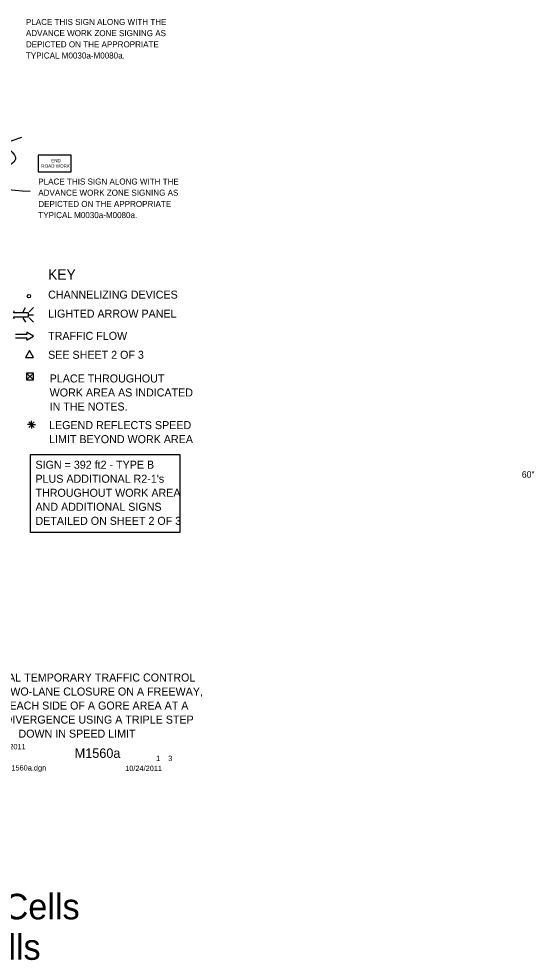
# Model space of a CAD drawing. Extents: x 16552 to 19508, y 5713 to 7079.
# Drawn here: x 17224 to 17823, y 5713 to 6807 of the extents above; entities that cross this region are included whole.
import ezdxf

# ---------------------------------------------------------------- set-up
doc = ezdxf.new("R2010")
doc.units = 0
for name, color, linetype in [('BORDER', 7, 'Continuous'), ('BORDER_SIGNAL_WO', 7, 'Continuous'), ('MT_SCRATCH_LEVEL_E', 7, 'Continuous'), ('PAVT_EDGE_EX', 7, 'Continuous'), ('TRAFFIC_SIGNS_PR', 7, 'Continuous'), ('TYPICAL_TEXT_DIMEN_EX', 7, 'Continuous'), ('TYPICAL_TEXT_DIMEN_PR', 7, 'Continuous')]:
    doc.layers.add(name, color=color, linetype=linetype)

msp = doc.modelspace()

# ---------------------------------------------------------------- linework, layer by layer
at = {"layer": 'MT_SCRATCH_LEVEL_E'}
for p, q in [((17233.4, 6441.9), (17233.7, 6440.1)), ((17241.3, 6438.3), (17234.1, 6442.4)), ((17233.7, 6440.1), (17220.5, 6440.1)), ((17220.5, 6436.4), (17233.7, 6436.4)), ((17233.7, 6436.4), (17233.4, 6434.6)), ((17234.1, 6434.1), (17241.3, 6438.3))]:
    msp.add_line(p, q, dxfattribs=at)
for centre, start, end in [((17233.9, 6442), 60.4248, 189.9638), ((17233.9, 6434.5), 170.0362, 299.7731)]:
    msp.add_arc(centre, 0.463, start, end, dxfattribs=at)
at = {"layer": 'PAVT_EDGE_EX'}
msp.add_arc((17319.9, 6383.8), 300, 107.923, 180, dxfattribs=at)
at = {"layer": 'TRAFFIC_SIGNS_PR'}
for p, q in [((17229.5, 6466.7), (17232.3, 6471.6)), ((17236.4, 6466.7), (17241.3, 6471.6)), ((17236.4, 6463.2), (17241.3, 6463.2)), ((17232.4, 6454.7), (17229.5, 6459.6)), ((17236.4, 6459.6), (17241.3, 6454.7))]:
    msp.add_line(p, q, dxfattribs=at)
msp.add_lwpolyline([(17246.9, 6629.2), (17285.3, 6629.2), (17285.3, 6648.4), (17246.9, 6648.4)], close=True, dxfattribs=at)
msp.add_lwpolyline([(17219.1, 6458.5), (17218.7, 6460.7), (17235.7, 6460.7), (17235.7, 6465.5), (17218.7, 6465.5), (17219.1, 6467.8)], dxfattribs=at)
msp.add_circle((17236.1, 6484.8), 2, dxfattribs=at)
at = {"layer": 'TYPICAL_TEXT_DIMEN_EX'}
msp.add_lwpolyline([(17237.9, 6300.7), (17411.6, 6300.7), (17411.6, 6210.4), (17237.9, 6210.4)], close=True, dxfattribs=at)
at = {"layer": 'TYPICAL_TEXT_DIMEN_PR'}
for p, q in [((17233.4, 6395.4), (17241.4, 6387.4)), ((17233.4, 6387.4), (17241.4, 6395.4)), ((17239.1, 6335.5), (17234.6, 6335.5)), ((17236, 6338.7), (17242.3, 6332.3)), ((17242.3, 6338.7), (17236, 6332.3)), ((17239.1, 6335.5), (17239.1, 6340)), ((17239.1, 6335.5), (17242.3, 6335.5)), ((17239.1, 6335.5), (17243.6, 6335.5)), ((17239.1, 6335.5), (17239.1, 6331))]:
    msp.add_line(p, q, dxfattribs=at)
for points in [[(17236.8, 6421.5), (17232.3, 6413.6), (17241.4, 6413.6)], [(17233.4, 6395.4), (17233.4, 6387.4), (17241.4, 6387.4), (17241.4, 6395.4)]]:
    msp.add_lwpolyline(points, close=True, dxfattribs=at)
msp.add_open_spline([(17211.5, 6657), (17216.4, 6652.5), (17226.4, 6643.1), (17205.5, 6632.6), (17175.7, 6610.9), (17212.4, 6608.3), (17237.4, 6606.6)], degree=3, dxfattribs=at)

# ---------------------------------------------------------------- texts
at = {"layer": 'BORDER'}
for s, p in [('TYPICAL TEMPORARY TRAFFIC CONTROL', (17175.2, 6037.1)), ('FOR A TWO-LANE CLOSURE ON A FREEWAY,', (17165.4, 6020.8)), ('ONE ON EACH SIDE OF A GORE AREA AT A ', (17160.9, 6004.5)), ('MAJOR DIVERGENCE USING A TRIPLE STEP ', (17160.9, 5988.2)), ('DOWN IN SPEED LIMIT', (17223.9, 5971.9))]:
    msp.add_text(s, height=9.3, dxfattribs=at).set_placement(p)
at = {"layer": 'BORDER_SIGNAL_WO'}
for s, height, p in [('    OCTOBER 2011    ', 6.2, (17159.1, 5958.3)), ('    M1560a   ', 11, (17272.9, 5948.4)), (' 1    3 ', 6.2, (17381.4, 5944.7)), ('PW RD/TS/Typicals/Signs/MT FWY/M1560a.dgn      ', 6.2, (17070.6, 5933.7)), ('10/24/2011    ', 6.2, (17347.9, 5933.1)), ('AS = 0.8 for Sign Cells', 29.727, (16894, 5760.8)), ('     1.0 for Text Cells', 29.727, (16894, 5713.8))]:
    msp.add_text(s, height=height, dxfattribs=at).set_placement(p)
at = {"layer": 'TRAFFIC_SIGNS_PR'}
for s, height, p in [('PLACE THIS SIGN ALONG WITH THE', 7, (17232.6, 6799.8)), ('ADVANCE WORK ZONE SIGNING AS', 7, (17232.6, 6786.8)), ('DEPICTED ON THE APPROPRIATE', 7, (17232.6, 6773.8)), ('TYPICAL M0030a-M0080a.', 7, (17232.6, 6760.8)), ('ROAD WORK', 3.83, (17250.5, 6634)), ('END', 3.83, (17261.9, 6640.3)), ('PLACE THIS SIGN ALONG WITH THE', 7, (17247, 6614.4)), ('ADVANCE WORK ZONE SIGNING AS', 7, (17247, 6601.4)), ('DEPICTED ON THE APPROPRIATE', 7, (17247, 6588.4)), ('TYPICAL M0030a-M0080a.', 7, (17247, 6575.4))]:
    msp.add_text(s, height=height, dxfattribs=at).set_placement(p)
at = {"layer": 'TYPICAL_TEXT_DIMEN_EX'}
for s, height, p in [('KEY', 12, (17258.4, 6503.9)), ('CHANNELIZING DEVICES', 9.3, (17258.4, 6481.9)), ('LIGHTED ARROW PANEL', 9.3, (17258.4, 6459.8)), ('TRAFFIC FLOW', 9.3, (17258.4, 6434)), ('SEE SHEET 2 OF 3', 9.3, (17258.4, 6412)), ('PLACE THROUGHOUT', 9.3, (17260.2, 6384.5)), ('WORK AREA AS INDICATED', 9.3, (17260.2, 6368.2)), ('IN THE NOTES.', 9.3, (17260.2, 6351.9)), ('LEGEND REFLECTS SPEED', 9.3, (17259.5, 6330.3)), ('LIMIT BEYOND WORK AREA', 9.3, (17259.5, 6314)), ('SIGN = 392 ft2 - TYPE B', 9.3, (17243.7, 6284.3)), ("PLUS ADDITIONAL R2-1's", 9.3, (17243.7, 6268)), ('THROUGHOUT WORK AREA', 9.3, (17243.7, 6251.7)), ('AND ADDITIONAL SIGNS', 9.3, (17243.7, 6235.4)), ('DETAILED ON SHEET 2 OF 3', 9.3, (17243.7, 6219.1))]:
    msp.add_text(s, height=height, dxfattribs=at).set_placement(p)
at = {"layer": 'TYPICAL_TEXT_DIMEN_PR'}
msp.add_text('60"', height=7.55, dxfattribs=at).set_placement((17808.9, 6273.9))

doc.saveas('drawing.dxf')
